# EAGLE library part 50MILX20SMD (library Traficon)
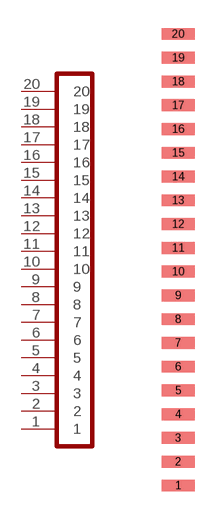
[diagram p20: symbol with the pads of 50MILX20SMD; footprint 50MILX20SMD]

Designator prefix HD

## 50MILX20SMD  [50MILX20SMD]
1  1  pas
2  2  pas
3  3  pas
4  4  pas
5  5  pas
6  6  pas
7  7  pas
8  8  pas
9  9  pas
10  10  pas
11  11  pas
12  12  pas
13  13  pas
14  14  pas
15  15  pas
16  16  pas
17  17  pas
18  18  pas
19  19  pas
20  20  pas

## Footprint 50MILX20SMD (pad centres in mm)
smd 1.778 x 0.635: 1 0,-12.065; 2 0,-10.795; 3 0,-9.525; 4 0,-8.255; 5 0,-6.985; 6 0,-5.715; 7 0,-4.445; 8 0,-3.175; 9 0,-1.905; 10 0,-0.635; 11 0,0.635; 12 0,1.905; 13 0,3.175; 14 0,4.445; 15 0,5.715; 16 0,6.985; 17 0,8.255; 18 0,9.525; 19 0,10.795; 20 0,12.065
